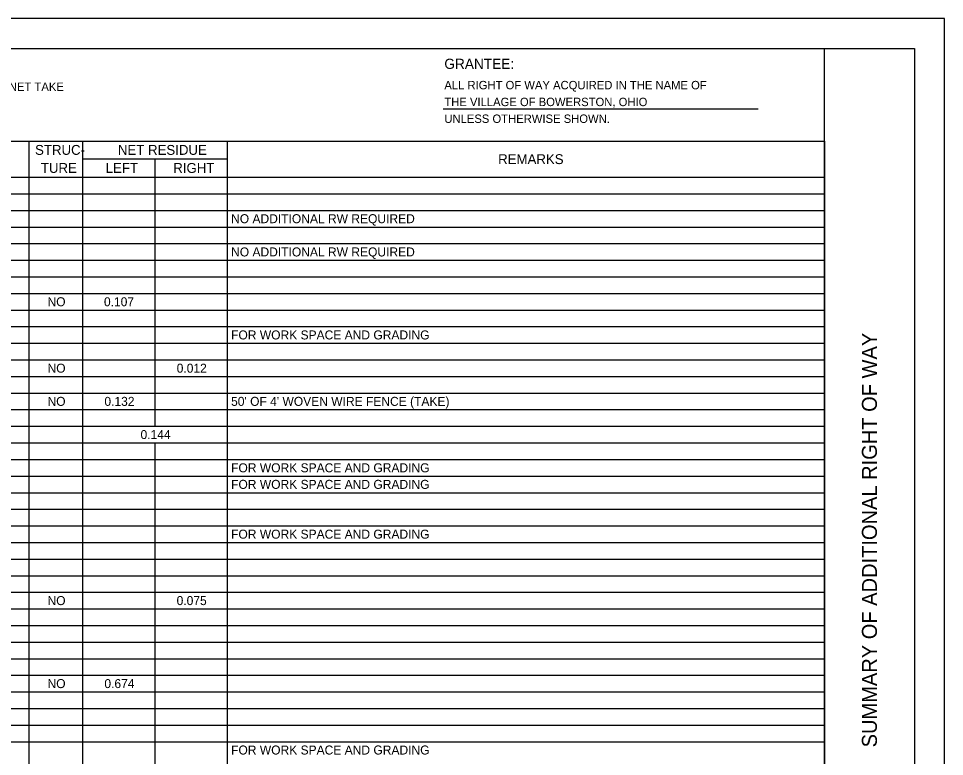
# Model space of a CAD drawing. Extents: x 0 to 34, y 0 to 22.
# Drawn here: x 18.58 to 34, y 9.7 to 22 of the extents above; entities that cross this region are included whole.
import ezdxf

# ---------------------------------------------------------------- set-up
doc = ezdxf.new("R2010")
doc.units = 0
for name, color, linetype in [('SH_Border', 7, 'Continuous'), ('SH_Cut_Line', 7, 'Continuous'), ('SH_Data', 7, 'Continuous'), ('SH_Text', 7, 'Continuous')]:
    doc.layers.add(name, color=color, linetype=linetype)

msp = doc.modelspace()

# ---------------------------------------------------------------- linework, layer by layer
at = {"layer": 'SH_Border'}
msp.add_line((32, 0.5), (32, 21.5), dxfattribs=at)
msp.add_lwpolyline([(1.5, 21.5), (33.5, 21.5), (33.5, 0.5), (1.5, 0.5)], close=True, dxfattribs=at)
at = {"layer": 'SH_Cut_Line'}
msp.add_lwpolyline([(0, 0), (34, 0), (34, 22), (0, 22)], close=True, dxfattribs=at)
at = {"layer": 'SH_Text'}
for p, q in [((25.651, 20.492), (30.9, 20.492)), ((1.5, 19.957), (32, 19.957)), ((18.752, 19.957), (18.752, 3.584)), ((19.647, 19.957), (19.647, 3.584)), ((22.056, 19.957), (22.056, 3.584)), ((32, 19.957), (32, 3.584)), ((19.647, 19.664), (22.056, 19.664)), ((20.851, 19.664), (20.851, 15.205)), ((1.5, 19.355), (32, 19.355)), ((1.5, 19.078), (32, 19.078)), ((1.5, 18.802), (32, 18.802)), ((1.5, 18.525), (32, 18.525)), ((1.5, 18.248), (32, 18.248)), ((1.5, 17.972), (32, 17.972)), ((1.5, 17.695), (32, 17.695)), ((1.5, 17.418), (32, 17.418)), ((1.5, 17.142), (32, 17.142)), ((1.5, 16.865), (32, 16.865)), ((1.5, 16.588), (32, 16.588)), ((1.5, 16.312), (32, 16.312)), ((1.5, 16.035), (32, 16.035)), ((1.5, 15.758), (32, 15.758)), ((1.5, 15.482), (32, 15.482)), ((1.5, 15.205), (32, 15.205)), ((1.5, 14.928), (32, 14.928)), ((20.851, 14.928), (20.851, 3.584)), ((1.5, 14.652), (32, 14.652)), ((1.5, 14.375), (32, 14.375)), ((1.5, 14.098), (32, 14.098)), ((1.5, 13.822), (32, 13.822)), ((1.5, 13.545), (32, 13.545)), ((1.5, 13.268), (32, 13.268)), ((1.5, 12.991), (32, 12.991)), ((1.5, 12.715), (32, 12.715)), ((1.5, 12.438), (32, 12.438)), ((1.5, 12.161), (32, 12.161)), ((1.5, 11.885), (32, 11.885)), ((1.5, 11.608), (32, 11.608)), ((1.5, 11.331), (32, 11.331)), ((1.5, 11.055), (32, 11.055)), ((1.5, 10.778), (32, 10.778)), ((1.5, 10.501), (32, 10.501)), ((1.5, 10.225), (32, 10.225)), ((1.5, 9.948), (32, 9.948))]:
    msp.add_line(p, q, dxfattribs=at)

# ---------------------------------------------------------------- texts
at = {"layer": 'SH_Data'}
msp.add_text('SUMMARY OF ADDITIONAL RIGHT OF WAY', height=0.25, rotation=90, dxfattribs=at).set_placement((32.875, 9.854))
at = {"layer": 'SH_Text'}
for s, height, p in [('GRANTEE:', 0.17, (25.672, 21.16)), ('NET RESIDUE = RECORD AREA - TOTAL PRO - NET TAKE', 0.14, (14.182, 20.793)), ('ALL RIGHT OF WAY ACQUIRED IN THE NAME OF', 0.14, (25.672, 20.82)), ('THE VILLAGE OF BOWERSTON, OHIO', 0.14, (25.672, 20.54)), ('UNLESS OTHERWISE SHOWN.', 0.14, (25.672, 20.26)), ('STRUC-', 0.1647, (18.857, 19.728)), ('NET RESIDUE', 0.16471, (20.236, 19.728)), ('REMARKS', 0.1647, (26.568, 19.574)), ('TURE', 0.1647, (18.953, 19.427)), ('LEFT', 0.1647, (20.033, 19.427)), ('RIGHT', 0.1647, (21.158, 19.427)), ('NO ADDITIONAL RW REQUIRED', 0.14973, (22.121, 18.589)), ('NO ADDITIONAL RW REQUIRED', 0.14973, (22.121, 18.035)), ('NO', 0.1497, (19.064, 17.205)), ('0.107', 0.1497, (20.004, 17.205)), ('FOR WORK SPACE AND GRADING', 0.14973, (22.121, 16.652)), ('NO', 0.1497, (19.064, 16.098)), ('0.012', 0.1497, (21.215, 16.098)), ('NO', 0.1497, (19.064, 15.545)), ('0.132', 0.1497, (20.011, 15.545)), ("50' OF 4' WOVEN WIRE FENCE (TAKE)", 0.14973, (22.121, 15.545)), ('0.144', 0.1497, (20.613, 14.992)), ('FOR WORK SPACE AND GRADING', 0.14973, (22.121, 14.438)), ('FOR WORK SPACE AND GRADING', 0.14973, (22.121, 14.162)), ('FOR WORK SPACE AND GRADING', 0.14973, (22.121, 13.332)), ('NO', 0.1497, (19.064, 12.225)), ('0.075', 0.1497, (21.214, 12.225)), ('NO', 0.1497, (19.064, 10.842)), ('0.674', 0.1497, (20.011, 10.842)), ('FOR WORK SPACE AND GRADING', 0.14973, (22.121, 9.735))]:
    msp.add_text(s, height=height, dxfattribs=at).set_placement(p)

doc.saveas('drawing.dxf')
